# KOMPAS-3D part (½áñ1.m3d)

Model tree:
1. Эскиз:1
2. Операция выдавливания:1
     Расстояние 1 = 20
3. Эскиз:2
4. Операция выдавливания:2
     Расстояние 1 = 400
5. Эскиз:3
6. Вырезать элемент выдавливания:1
     Расстояние 1 = 70
7. Эскиз:4
8. Вырезать элемент выдавливания:2
     Расстояние 1 = 2
9. Эскиз:5
10. Эскиз:11
11. Вырезать элемент выдавливания:7
     Расстояние 1 = 30
12. Эскиз:12
13. Вырезать элемент выдавливания:8
     Расстояние 1 = 30
